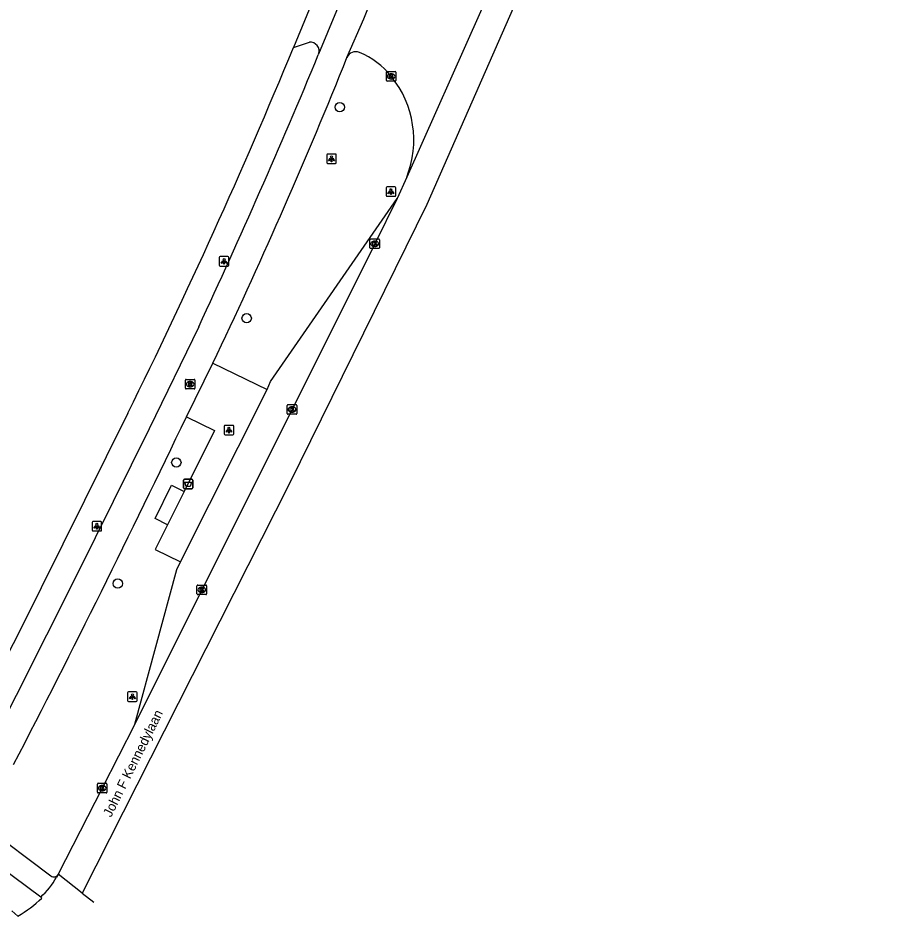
# Model space of a CAD drawing. Extents: x 161243 to 161752, y 384138 to 384885.
# Drawn here: x 161651.8 to 161744, y 384604.9 to 384698.8 of the extents above; entities that cross this region are included whole.
import ezdxf

# ---------------------------------------------------------------- set-up
doc = ezdxf.new("R2010")
doc.units = 0
for name, color, linetype in [('IMGEO_Afvalbak', 7, 'Continuous'), ('IMGEO_Boom', 7, 'Continuous'), ('IMGEO_Fietspad_gesloten', 7, 'Continuous'), ('IMGEO_Kolk', 7, 'Continuous'), ('IMGEO_Lichtpunt', 7, 'Continuous'), ('IMGEO_Openbare_ruimte_label', 7, 'Continuous'), ('IMGEO_OVBaan_gesloten', 7, 'Continuous'), ('IMGEO_Rijbaan_lokaal_gesloten', 7, 'Continuous'), ('IMGEO_Rijbaan_lokaal_open', 7, 'Continuous'), ('IMGEO_Rioolput', 7, 'Continuous'), ('IMGEO_Voetpad_gesloten', 7, 'Continuous'), ('IMGEO_Voetpad_open', 7, 'Continuous')]:
    doc.layers.add(name, color=color, linetype=linetype)

msp = doc.modelspace()

# ---------------------------------------------------------------- linework, layer by layer
at = {"layer": 'IMGEO_Afvalbak'}
for p, q in [((161669.103, 384649.619), (161669.103, 384650.419)), ((161669.103, 384650.419), (161669.103, 384649.619)), ((161669.203, 384650.519), (161669.993, 384650.519)), ((161669.993, 384650.519), (161669.203, 384650.519)), ((161670.093, 384650.419), (161670.093, 384649.619)), ((161670.093, 384649.619), (161670.093, 384650.419)), ((161669.993, 384649.519), (161669.203, 384649.519)), ((161669.203, 384649.519), (161669.993, 384649.519))]:
    msp.add_line(p, q, dxfattribs=at)
msp.add_lwpolyline([(161669.246, 384650.233), (161669.95, 384650.233), (161669.801, 384649.763), (161669.395, 384649.763), (161669.246, 384650.233)], dxfattribs=at)
for centre, start, end in [((161669.203, 384650.419), 90, 180), ((161669.203, 384650.419), 90, 180), ((161669.993, 384650.419), 0, 90), ((161669.993, 384650.419), 360, 90), ((161669.203, 384649.619), 180, 270), ((161669.203, 384649.619), 180, 270), ((161669.993, 384649.619), 270, 0), ((161669.993, 384649.619), 270, 0)]:
    msp.add_arc(centre, 0.1, start, end, dxfattribs=at)
at = {"layer": 'IMGEO_Boom'}
for centre in [(161685.446, 384689.434), (161675.717, 384667.363), (161668.362, 384652.278), (161662.235, 384639.611)]:
    msp.add_circle(centre, 0.489, dxfattribs=at)
at = {"layer": 'IMGEO_Fietspad_gesloten'}
for points in [[(161683.241, 384694.978), (161683.21, 384694.903)], [(161685.831, 384693.677), (161686.187, 384694.645)], [(161670.701, 384666.467), (161665.518, 384655.805), (161657.99, 384640.592), (161648.37, 384621.531), (161646.258, 384617.415)], [(161669.414, 384657.064), (161672.189, 384662.664)], [(161654.174, 384606.822), (161646.797, 384612.297), (161647.827, 384614.44), (161648.083, 384614.913)]]:
    msp.add_lwpolyline(points, dxfattribs=at)
for centre, radius, start, end in [((161009.658, 384974.229), 729.175, 335.034693, 337.475907), ((161170.909, 384901.674), 555.344, 334.50822, 338.00431), ((160576.681, 385177.208), 1210.213, 332.622188, 334.545441)]:
    msp.add_arc(centre, radius, start, end, dxfattribs=at)
at = {"layer": 'IMGEO_Kolk'}
for p, q in [((161690.332, 384692.231), (161690.332, 384693.083)), ((161690.407, 384693.157), (161691.259, 384693.157)), ((161691.333, 384693.083), (161691.333, 384692.231)), ((161691.259, 384692.157), (161690.407, 384692.157)), ((161690.843, 384692.377), (161690.818, 384692.377)), ((161690.82, 384692.937), (161690.845, 384692.937)), ((161688.605, 384674.726), (161688.605, 384675.578)), ((161688.68, 384675.652), (161689.532, 384675.652)), ((161689.093, 384675.432), (161689.118, 384675.432)), ((161689.606, 384675.578), (161689.606, 384674.726)), ((161689.532, 384674.652), (161688.68, 384674.652)), ((161689.116, 384674.872), (161689.091, 384674.872)), ((161680.036, 384658.327), (161680.888, 384658.327)), ((161679.961, 384657.401), (161679.961, 384658.253)), ((161680.888, 384657.327), (161680.036, 384657.327)), ((161680.472, 384657.547), (161680.447, 384657.547)), ((161680.449, 384658.107), (161680.474, 384658.107)), ((161680.962, 384658.253), (161680.962, 384657.401)), ((161670.523, 384638.54), (161670.523, 384639.392)), ((161670.598, 384639.466), (161671.45, 384639.466)), ((161671.034, 384638.686), (161671.009, 384638.686)), ((161671.011, 384639.246), (161671.036, 384639.246)), ((161671.524, 384639.392), (161671.524, 384638.54)), ((161671.45, 384638.466), (161670.598, 384638.466)), ((161660.107, 384617.804), (161660.107, 384618.656)), ((161660.182, 384618.73), (161661.034, 384618.73)), ((161660.618, 384617.95), (161660.593, 384617.95)), ((161660.595, 384618.51), (161660.62, 384618.51)), ((161661.108, 384618.656), (161661.108, 384617.804)), ((161661.034, 384617.73), (161660.182, 384617.73))]:
    msp.add_line(p, q, dxfattribs=at)
for points in [[(161690.332, 384692.231), (161690.332, 384693.083)], [(161690.407, 384693.157), (161691.259, 384693.157)], [(161691.333, 384693.083), (161691.333, 384692.231)], [(161691.259, 384692.157), (161690.407, 384692.157)], [(161690.653, 384692.857), (161690.776, 384692.857), (161690.776, 384692.706), (161690.906, 384692.857), (161691.07, 384692.857), (161690.924, 384692.706), (161691.077, 384692.457), (161690.925, 384692.457), (161690.84, 384692.621), (161690.776, 384692.554), (161690.776, 384692.457), (161690.653, 384692.457), (161690.653, 384692.857)], [(161688.605, 384674.726), (161688.605, 384675.578)], [(161688.68, 384675.652), (161689.532, 384675.652)], [(161688.926, 384675.352), (161689.049, 384675.352), (161689.049, 384675.201), (161689.179, 384675.352), (161689.343, 384675.352), (161689.197, 384675.201), (161689.35, 384674.952), (161689.198, 384674.952), (161689.113, 384675.116), (161689.049, 384675.049), (161689.049, 384674.952), (161688.926, 384674.952), (161688.926, 384675.352)], [(161689.606, 384675.578), (161689.606, 384674.726)], [(161689.532, 384674.652), (161688.68, 384674.652)], [(161680.036, 384658.327), (161680.888, 384658.327)], [(161679.961, 384657.401), (161679.961, 384658.253)], [(161680.888, 384657.327), (161680.036, 384657.327)], [(161680.282, 384658.027), (161680.405, 384658.027), (161680.405, 384657.876), (161680.535, 384658.027), (161680.699, 384658.027), (161680.553, 384657.876), (161680.706, 384657.627), (161680.554, 384657.627), (161680.469, 384657.791), (161680.405, 384657.724), (161680.405, 384657.627), (161680.282, 384657.627), (161680.282, 384658.027)], [(161680.962, 384658.253), (161680.962, 384657.401)], [(161670.523, 384638.54), (161670.523, 384639.392)], [(161670.598, 384639.466), (161671.45, 384639.466)], [(161670.844, 384639.166), (161670.967, 384639.166), (161670.967, 384639.015), (161671.097, 384639.166), (161671.261, 384639.166), (161671.115, 384639.015), (161671.268, 384638.766), (161671.116, 384638.766), (161671.031, 384638.93), (161670.967, 384638.863), (161670.967, 384638.766), (161670.844, 384638.766), (161670.844, 384639.166)], [(161671.524, 384639.392), (161671.524, 384638.54)], [(161671.45, 384638.466), (161670.598, 384638.466)], [(161660.107, 384617.804), (161660.107, 384618.656)], [(161660.182, 384618.73), (161661.034, 384618.73)], [(161660.428, 384618.43), (161660.551, 384618.43), (161660.551, 384618.279), (161660.681, 384618.43), (161660.845, 384618.43), (161660.699, 384618.279), (161660.852, 384618.03), (161660.7, 384618.03), (161660.615, 384618.194), (161660.551, 384618.127), (161660.551, 384618.03), (161660.428, 384618.03), (161660.428, 384618.43)], [(161661.108, 384618.656), (161661.108, 384617.804)], [(161661.034, 384617.73), (161660.182, 384617.73)]]:
    msp.add_lwpolyline(points, dxfattribs=at)
for centre, start, end in [((161690.409, 384693.081), 91.55205, 178.44795), ((161690.409, 384693.081), 91.55205, 178.44795), ((161691.257, 384693.081), 1.55205, 88.44795), ((161691.257, 384693.081), 1.55205, 88.44795), ((161690.409, 384692.233), 181.55205, 268.44795), ((161690.409, 384692.233), 181.55205, 268.44795), ((161691.257, 384692.233), 271.55205, 358.44795), ((161691.257, 384692.233), 271.55205, 358.44795), ((161688.682, 384675.576), 91.55205, 178.44795), ((161688.682, 384675.576), 91.55205, 178.44795), ((161689.53, 384675.576), 1.55205, 88.44795), ((161689.53, 384675.576), 1.55205, 88.44795), ((161688.682, 384674.728), 181.55205, 268.44795), ((161688.682, 384674.728), 181.55205, 268.44795), ((161689.53, 384674.728), 271.55205, 358.44795), ((161689.53, 384674.728), 271.55205, 358.44795), ((161680.038, 384658.251), 91.55205, 178.44795), ((161680.038, 384658.251), 91.55205, 178.44795), ((161680.886, 384658.251), 1.55205, 88.44795), ((161680.886, 384658.251), 1.55205, 88.44795), ((161680.038, 384657.403), 181.55205, 268.44795), ((161680.038, 384657.403), 181.55205, 268.44795), ((161680.886, 384657.403), 271.55205, 358.44795), ((161680.886, 384657.403), 271.55205, 358.44795), ((161670.6, 384639.39), 91.55205, 178.44795), ((161670.6, 384639.39), 91.55205, 178.44795), ((161671.448, 384639.39), 1.55205, 88.44795), ((161671.448, 384639.39), 1.55205, 88.44795), ((161670.6, 384638.542), 181.55205, 268.44795), ((161670.6, 384638.542), 181.55205, 268.44795), ((161671.448, 384638.542), 271.55205, 358.44795), ((161671.448, 384638.542), 271.55205, 358.44795), ((161660.184, 384618.654), 91.55205, 178.44795), ((161660.184, 384618.654), 91.55205, 178.44795), ((161661.032, 384618.654), 1.55205, 88.44795), ((161661.032, 384618.654), 1.55205, 88.44795), ((161660.184, 384617.806), 181.55205, 268.44795), ((161660.184, 384617.806), 181.55205, 268.44795), ((161661.032, 384617.806), 271.55205, 358.44795), ((161661.032, 384617.806), 271.55205, 358.44795)]:
    msp.add_arc(centre, 0.0765, start, end, dxfattribs=at)
for centre, major_axis, ratio, start_param, end_param in [((161690.819, 384692.657), (-0.387, 0.002), 0.722429, 4.712389, 7.853982), ((161690.844, 384692.657), (-0.39, 0.002), 0.717154, 1.570796, 4.712389), ((161689.092, 384675.152), (-0.387, 0.002), 0.722429, 4.712389, 7.853982), ((161689.117, 384675.152), (-0.39, 0.002), 0.717154, 1.570796, 4.712389), ((161680.448, 384657.827), (-0.387, 0.002), 0.722429, 4.712389, 7.853982), ((161680.473, 384657.827), (-0.39, 0.002), 0.717154, 1.570796, 4.712389), ((161671.01, 384638.966), (-0.387, 0.002), 0.722429, 4.712389, 7.853982), ((161671.035, 384638.966), (-0.39, 0.002), 0.717154, 1.570796, 4.712389), ((161660.594, 384618.23), (-0.387, 0.002), 0.722429, 4.712389, 7.853982), ((161660.619, 384618.23), (-0.39, 0.002), 0.717154, 1.570796, 4.712389)]:
    msp.add_ellipse(centre, major_axis=major_axis, ratio=ratio, start_param=start_param, end_param=end_param, dxfattribs=at)
at = {"layer": 'IMGEO_Lichtpunt'}
for p, q in [((161684.092, 384684.437), (161684.092, 384683.63)), ((161684.092, 384684.437), (161684.092, 384683.63)), ((161684.994, 384684.532), (161684.186, 384684.532)), ((161684.994, 384684.532), (161684.186, 384684.532)), ((161685.088, 384683.63), (161685.088, 384684.437)), ((161685.088, 384683.63), (161685.088, 384684.437)), ((161684.186, 384683.536), (161684.994, 384683.536)), ((161684.186, 384683.536), (161684.994, 384683.536)), ((161690.309, 384681.014), (161690.309, 384680.207)), ((161690.309, 384681.014), (161690.309, 384680.207)), ((161691.211, 384681.109), (161690.403, 384681.109)), ((161691.211, 384681.109), (161690.403, 384681.109)), ((161691.305, 384680.207), (161691.305, 384681.014)), ((161691.305, 384680.207), (161691.305, 384681.014)), ((161690.403, 384680.113), (161691.211, 384680.113)), ((161690.403, 384680.113), (161691.211, 384680.113)), ((161672.855, 384673.712), (161672.855, 384672.905)), ((161672.855, 384673.712), (161672.855, 384672.905)), ((161673.757, 384673.807), (161672.949, 384673.807)), ((161673.757, 384673.807), (161672.949, 384673.807)), ((161673.851, 384672.905), (161673.851, 384673.712)), ((161673.851, 384672.905), (161673.851, 384673.712)), ((161672.949, 384672.811), (161673.757, 384672.811)), ((161672.949, 384672.811), (161673.757, 384672.811)), ((161673.37, 384656.067), (161673.37, 384655.26)), ((161673.37, 384656.067), (161673.37, 384655.26)), ((161674.272, 384656.162), (161673.464, 384656.162)), ((161674.272, 384656.162), (161673.464, 384656.162)), ((161674.366, 384655.26), (161674.366, 384656.067)), ((161674.366, 384655.26), (161674.366, 384656.067)), ((161673.464, 384655.166), (161674.272, 384655.166)), ((161673.464, 384655.166), (161674.272, 384655.166)), ((161660.454, 384646.115), (161659.646, 384646.115)), ((161660.454, 384646.115), (161659.646, 384646.115)), ((161659.552, 384646.02), (161659.552, 384645.213)), ((161659.552, 384646.02), (161659.552, 384645.213)), ((161659.646, 384645.119), (161660.454, 384645.119)), ((161659.646, 384645.119), (161660.454, 384645.119)), ((161660.548, 384645.213), (161660.548, 384646.02)), ((161660.548, 384645.213), (161660.548, 384646.02)), ((161664.172, 384628.286), (161663.364, 384628.286)), ((161664.172, 384628.286), (161663.364, 384628.286)), ((161663.27, 384628.191), (161663.27, 384627.384)), ((161663.27, 384628.191), (161663.27, 384627.384)), ((161663.364, 384627.29), (161664.172, 384627.29)), ((161663.364, 384627.29), (161664.172, 384627.29)), ((161664.266, 384627.384), (161664.266, 384628.191)), ((161664.266, 384627.384), (161664.266, 384628.191))]:
    msp.add_line(p, q, dxfattribs=at)
for points in [[(161684.466, 384684.101), (161684.505, 384684.073), (161684.317, 384683.811), (161684.279, 384683.838), (161684.466, 384684.101)], [(161684.568, 384684.053), (161684.615, 384684.053), (161684.615, 384683.731), (161684.568, 384683.731), (161684.568, 384684.053)], [(161684.678, 384684.073), (161684.716, 384684.1), (161684.903, 384683.838), (161684.864, 384683.81), (161684.678, 384684.073)], [(161690.683, 384680.678), (161690.722, 384680.65), (161690.534, 384680.388), (161690.496, 384680.415), (161690.683, 384680.678)], [(161690.785, 384680.63), (161690.832, 384680.63), (161690.832, 384680.308), (161690.785, 384680.308), (161690.785, 384680.63)], [(161690.895, 384680.65), (161690.933, 384680.677), (161691.12, 384680.415), (161691.081, 384680.387), (161690.895, 384680.65)], [(161673.229, 384673.376), (161673.268, 384673.348), (161673.08, 384673.086), (161673.042, 384673.113), (161673.229, 384673.376)], [(161673.331, 384673.328), (161673.378, 384673.328), (161673.378, 384673.006), (161673.331, 384673.006), (161673.331, 384673.328)], [(161673.441, 384673.348), (161673.479, 384673.375), (161673.666, 384673.113), (161673.627, 384673.085), (161673.441, 384673.348)], [(161673.744, 384655.731), (161673.783, 384655.703), (161673.595, 384655.441), (161673.557, 384655.468), (161673.744, 384655.731)], [(161673.846, 384655.683), (161673.893, 384655.683), (161673.893, 384655.361), (161673.846, 384655.361), (161673.846, 384655.683)], [(161673.956, 384655.703), (161673.994, 384655.73), (161674.181, 384655.468), (161674.142, 384655.44), (161673.956, 384655.703)], [(161659.926, 384645.684), (161659.965, 384645.656), (161659.777, 384645.394), (161659.739, 384645.421), (161659.926, 384645.684)], [(161660.028, 384645.636), (161660.075, 384645.636), (161660.075, 384645.314), (161660.028, 384645.314), (161660.028, 384645.636)], [(161660.138, 384645.656), (161660.176, 384645.683), (161660.363, 384645.421), (161660.324, 384645.393), (161660.138, 384645.656)], [(161663.644, 384627.855), (161663.683, 384627.827), (161663.495, 384627.565), (161663.457, 384627.592), (161663.644, 384627.855)], [(161663.746, 384627.807), (161663.793, 384627.807), (161663.793, 384627.485), (161663.746, 384627.485), (161663.746, 384627.807)], [(161663.856, 384627.827), (161663.894, 384627.854), (161664.081, 384627.592), (161664.042, 384627.564), (161663.856, 384627.827)]]:
    msp.add_lwpolyline(points, dxfattribs=at)
for centre in [(161684.591, 384684.235), (161690.808, 384680.812), (161673.354, 384673.51), (161673.869, 384655.865), (161660.051, 384645.818), (161663.769, 384627.989)]:
    msp.add_circle(centre, 0.0994, dxfattribs=at)
for centre, start, end in [((161684.186, 384684.437), 90, 180), ((161684.186, 384684.437), 90, 180), ((161684.186, 384683.63), 180, 270), ((161684.186, 384683.63), 180, 270), ((161684.994, 384684.437), 0, 90), ((161684.994, 384684.437), 0, 90), ((161684.994, 384683.63), 270, 0), ((161684.994, 384683.63), 270, 360), ((161690.403, 384681.014), 90, 180), ((161690.403, 384681.014), 90, 180), ((161691.211, 384681.014), 0, 90), ((161691.211, 384681.014), 0, 90), ((161690.403, 384680.207), 180, 270), ((161690.403, 384680.207), 180, 270), ((161691.211, 384680.207), 270, 0), ((161691.211, 384680.207), 270, 360), ((161672.949, 384673.712), 90, 180), ((161672.949, 384673.712), 90, 180), ((161673.757, 384673.712), 0, 90), ((161673.757, 384673.712), 0, 90), ((161672.949, 384672.905), 180, 270), ((161672.949, 384672.905), 180, 270), ((161673.757, 384672.905), 270, 0), ((161673.757, 384672.905), 270, 360), ((161673.464, 384656.067), 90, 180), ((161673.464, 384656.067), 90, 180), ((161674.272, 384656.067), 0, 90), ((161674.272, 384656.067), 0, 90), ((161673.464, 384655.26), 180, 270), ((161673.464, 384655.26), 180, 270), ((161674.272, 384655.26), 270, 0), ((161674.272, 384655.26), 270, 360), ((161659.646, 384646.02), 90, 180), ((161659.646, 384646.02), 90, 180), ((161660.454, 384646.02), 0, 90), ((161660.454, 384646.02), 0, 90), ((161659.646, 384645.213), 180, 270), ((161659.646, 384645.213), 180, 270), ((161660.454, 384645.213), 270, 0), ((161660.454, 384645.213), 270, 360), ((161663.364, 384628.191), 90, 180), ((161663.364, 384628.191), 90, 180), ((161664.172, 384628.191), 0, 90), ((161664.172, 384628.191), 0, 90), ((161663.364, 384627.384), 180, 270), ((161663.364, 384627.384), 180, 270), ((161664.172, 384627.384), 270, 0), ((161664.172, 384627.384), 270, 360)]:
    msp.add_arc(centre, 0.0946, start, end, dxfattribs=at)
at = {"layer": 'IMGEO_OVBaan_gesloten'}
for points in [[(161691.462, 384679.879), (161689.106, 384675.152), (161680.462, 384657.827), (161671.024, 384638.966), (161664.011, 384624.923)], [(161677.855, 384659.925), (161678.224, 384660.756), (161691.462, 384679.879)], [(161668.794, 384641.885), (161677.855, 384659.925)], [(161664.011, 384624.923), (161668.425, 384641.073), (161668.794, 384641.885)]]:
    msp.add_lwpolyline(points, dxfattribs=at)
at = {"layer": 'IMGEO_Rijbaan_lokaal_gesloten'}
for points in [[(161744.047, 384816.284), (161742.448, 384808.757), (161735.777, 384786.652), (161725.575, 384756.83), (161716.255, 384732.828), (161712.723, 384722.298), (161707.131, 384707.91), (161694.574, 384679.263), (161680.185, 384650.094), (161667.104, 384624.194), (161658.512, 384607.257)], [(161732, 384785.935), (161730.383, 384780.965), (161728.143, 384774.32), (161726.12, 384768.434), (161723.421, 384760.654), (161722.08, 384756.881), (161721.701, 384755.958), (161712.778, 384731.315), (161700.185, 384699.405), (161692.45, 384682.113)], [(161686.187, 384694.645), (161687.981, 384698.686), (161689.438, 384702.388)], [(161692.45, 384682.113), (161691.462, 384679.879)], [(161664.011, 384624.923), (161660.608, 384618.23), (161656.018, 384609.223)], [(161656.018, 384609.223), (161656.016, 384609.19), (161655.845, 384608.91)], [(161658.512, 384607.257), (161656.018, 384609.223)], [(161654.174, 384606.822), (161654.299, 384606.723)], [(161658.512, 384607.257), (161659.742, 384606.287)], [(161651.799, 384604.852), (161651.142, 384605.383)]]:
    msp.add_lwpolyline(points, dxfattribs=at)
for centre, radius, start, end in [((161687.128, 384694.194), 1.044, 68.41067, 154.3697), ((161684.182, 384687.3), 8.54, 38.85151, 67.05068), ((161682.649, 384686.006), 10.546, 338.33781, 39.09979), ((161648.216, 384613.302), 8.803, 312.59298, 330.06733), ((161644.427, 384617.307), 14.473, 300.6184, 313.00397)]:
    msp.add_arc(centre, radius, start, end, dxfattribs=at)
at = {"layer": 'IMGEO_Rijbaan_lokaal_open'}
for points in [[(161686.063, 384701.814), (161683.241, 384694.978)], [(161682.917, 384701.297), (161680.865, 384696.273), (161680.626, 384695.691)], [(161680.626, 384695.691), (161682.271, 384696.228)]]:
    msp.add_lwpolyline(points, dxfattribs=at)
msp.add_arc((161682.362, 384695.297), 0.935, 340.05184, 95.57109, dxfattribs=at)
at = {"layer": 'IMGEO_Rioolput'}
for p, q in [((161669.312, 384660.039), (161669.312, 384660.891)), ((161669.387, 384660.965), (161670.239, 384660.965)), ((161669.823, 384660.185), (161669.798, 384660.185)), ((161669.8, 384660.745), (161669.825, 384660.745)), ((161670.313, 384660.891), (161670.313, 384660.039)), ((161670.239, 384659.965), (161669.387, 384659.965))]:
    msp.add_line(p, q, dxfattribs=at)
for points in [[(161669.312, 384660.039), (161669.312, 384660.891)], [(161669.387, 384660.965), (161670.239, 384660.965)], [(161669.901, 384660.663), (161669.649, 384660.665), (161669.649, 384660.265)], [(161669.649, 384660.265), (161669.773, 384660.265), (161669.773, 384660.427), (161669.784, 384660.427)], [(161669.827, 384660.584), (161669.773, 384660.584), (161669.773, 384660.503)], [(161669.773, 384660.503), (161669.825, 384660.503)], [(161669.831, 384660.398), (161669.902, 384660.265), (161670.042, 384660.265), (161669.977, 384660.391)], [(161670.313, 384660.891), (161670.313, 384660.039)], [(161670.239, 384659.965), (161669.387, 384659.965)]]:
    msp.add_lwpolyline(points, dxfattribs=at)
for centre, radius, start, end in [((161669.389, 384660.889), 0.0765, 91.55205, 178.44795), ((161669.389, 384660.889), 0.0765, 91.55205, 178.44795), ((161669.783, 384660.374), 0.0533, 26.02933, 88.69889), ((161669.809, 384660.692), 0.19, 274.7715, 282.96867), ((161669.833, 384660.488), 0.0964, 77.00612, 93.18647), ((161669.847, 384660.545), 0.0378, 276.66336, 79.67722), ((161669.9, 384660.553), 0.109, 350.36119, 89.41601), ((161669.898, 384660.553), 0.112, 277.58423, 350.98172), ((161669.882, 384660.338), 0.108, 29.51342, 73.79051), ((161670.237, 384660.889), 0.0765, 1.55205, 88.44795), ((161670.237, 384660.889), 0.0765, 1.55205, 88.44795), ((161669.389, 384660.041), 0.0765, 181.55205, 268.44795), ((161669.389, 384660.041), 0.0765, 181.55205, 268.44795), ((161670.237, 384660.041), 0.0765, 271.55205, 358.44795), ((161670.237, 384660.041), 0.0765, 271.55205, 358.44795)]:
    msp.add_arc(centre, radius, start, end, dxfattribs=at)
for centre, major_axis, ratio, start_param, end_param in [((161669.799, 384660.465), (-0.387, 0.002), 0.722429, 4.712389, 7.853982), ((161669.824, 384660.465), (-0.39, 0.002), 0.717154, 1.570796, 4.712389)]:
    msp.add_ellipse(centre, major_axis=major_axis, ratio=ratio, start_param=start_param, end_param=end_param, dxfattribs=at)
at = {"layer": 'IMGEO_Voetpad_gesloten'}
for points in [[(161667.442, 384645.768), (161666.144, 384646.412), (161667.864, 384649.891), (161669.17, 384649.244)], [(161669.17, 384649.244), (161667.442, 384645.768)]]:
    msp.add_lwpolyline(points, dxfattribs=at)
at = {"layer": 'IMGEO_Voetpad_open'}
for points in [[(161672.189, 384662.664), (161677.855, 384659.925)], [(161663.295, 384657.439), (161651.971, 384634.614), (161649.293, 384629.449)], [(161669.414, 384657.064), (161672.338, 384655.608), (161669.17, 384649.244)], [(161667.442, 384645.768), (161666.149, 384643.196), (161668.794, 384641.885)], [(161648.258, 384614.28), (161655.238, 384609.045)]]:
    msp.add_lwpolyline(points, dxfattribs=at)
for centre, radius, start, end in [((161101.188, 384935.167), 626.975, 333.706735, 337.545143), ((161655.548, 384609.485), 0.538, 234.84609, 330.86402)]:
    msp.add_arc(centre, radius, start, end, dxfattribs=at)

# ---------------------------------------------------------------- texts
at = {"layer": 'IMGEO_Openbare_ruimte_label'}
msp.add_text('John F Kennedylaan', height=1, rotation=63.56313, dxfattribs=at).set_placement((161661.536, 384615.117))

doc.saveas('drawing.dxf')
